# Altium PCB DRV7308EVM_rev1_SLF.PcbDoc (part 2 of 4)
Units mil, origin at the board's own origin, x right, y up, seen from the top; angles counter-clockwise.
Board outline 6187 x 6000 mil, 4 copper layers (Top Layer, Ground, Power, Bottom Layer), stack 61.2 mil thick; 306 components, 128 nets, 676 pads, 1026 vias.
Unrouted connection lines stored in the file: 208.
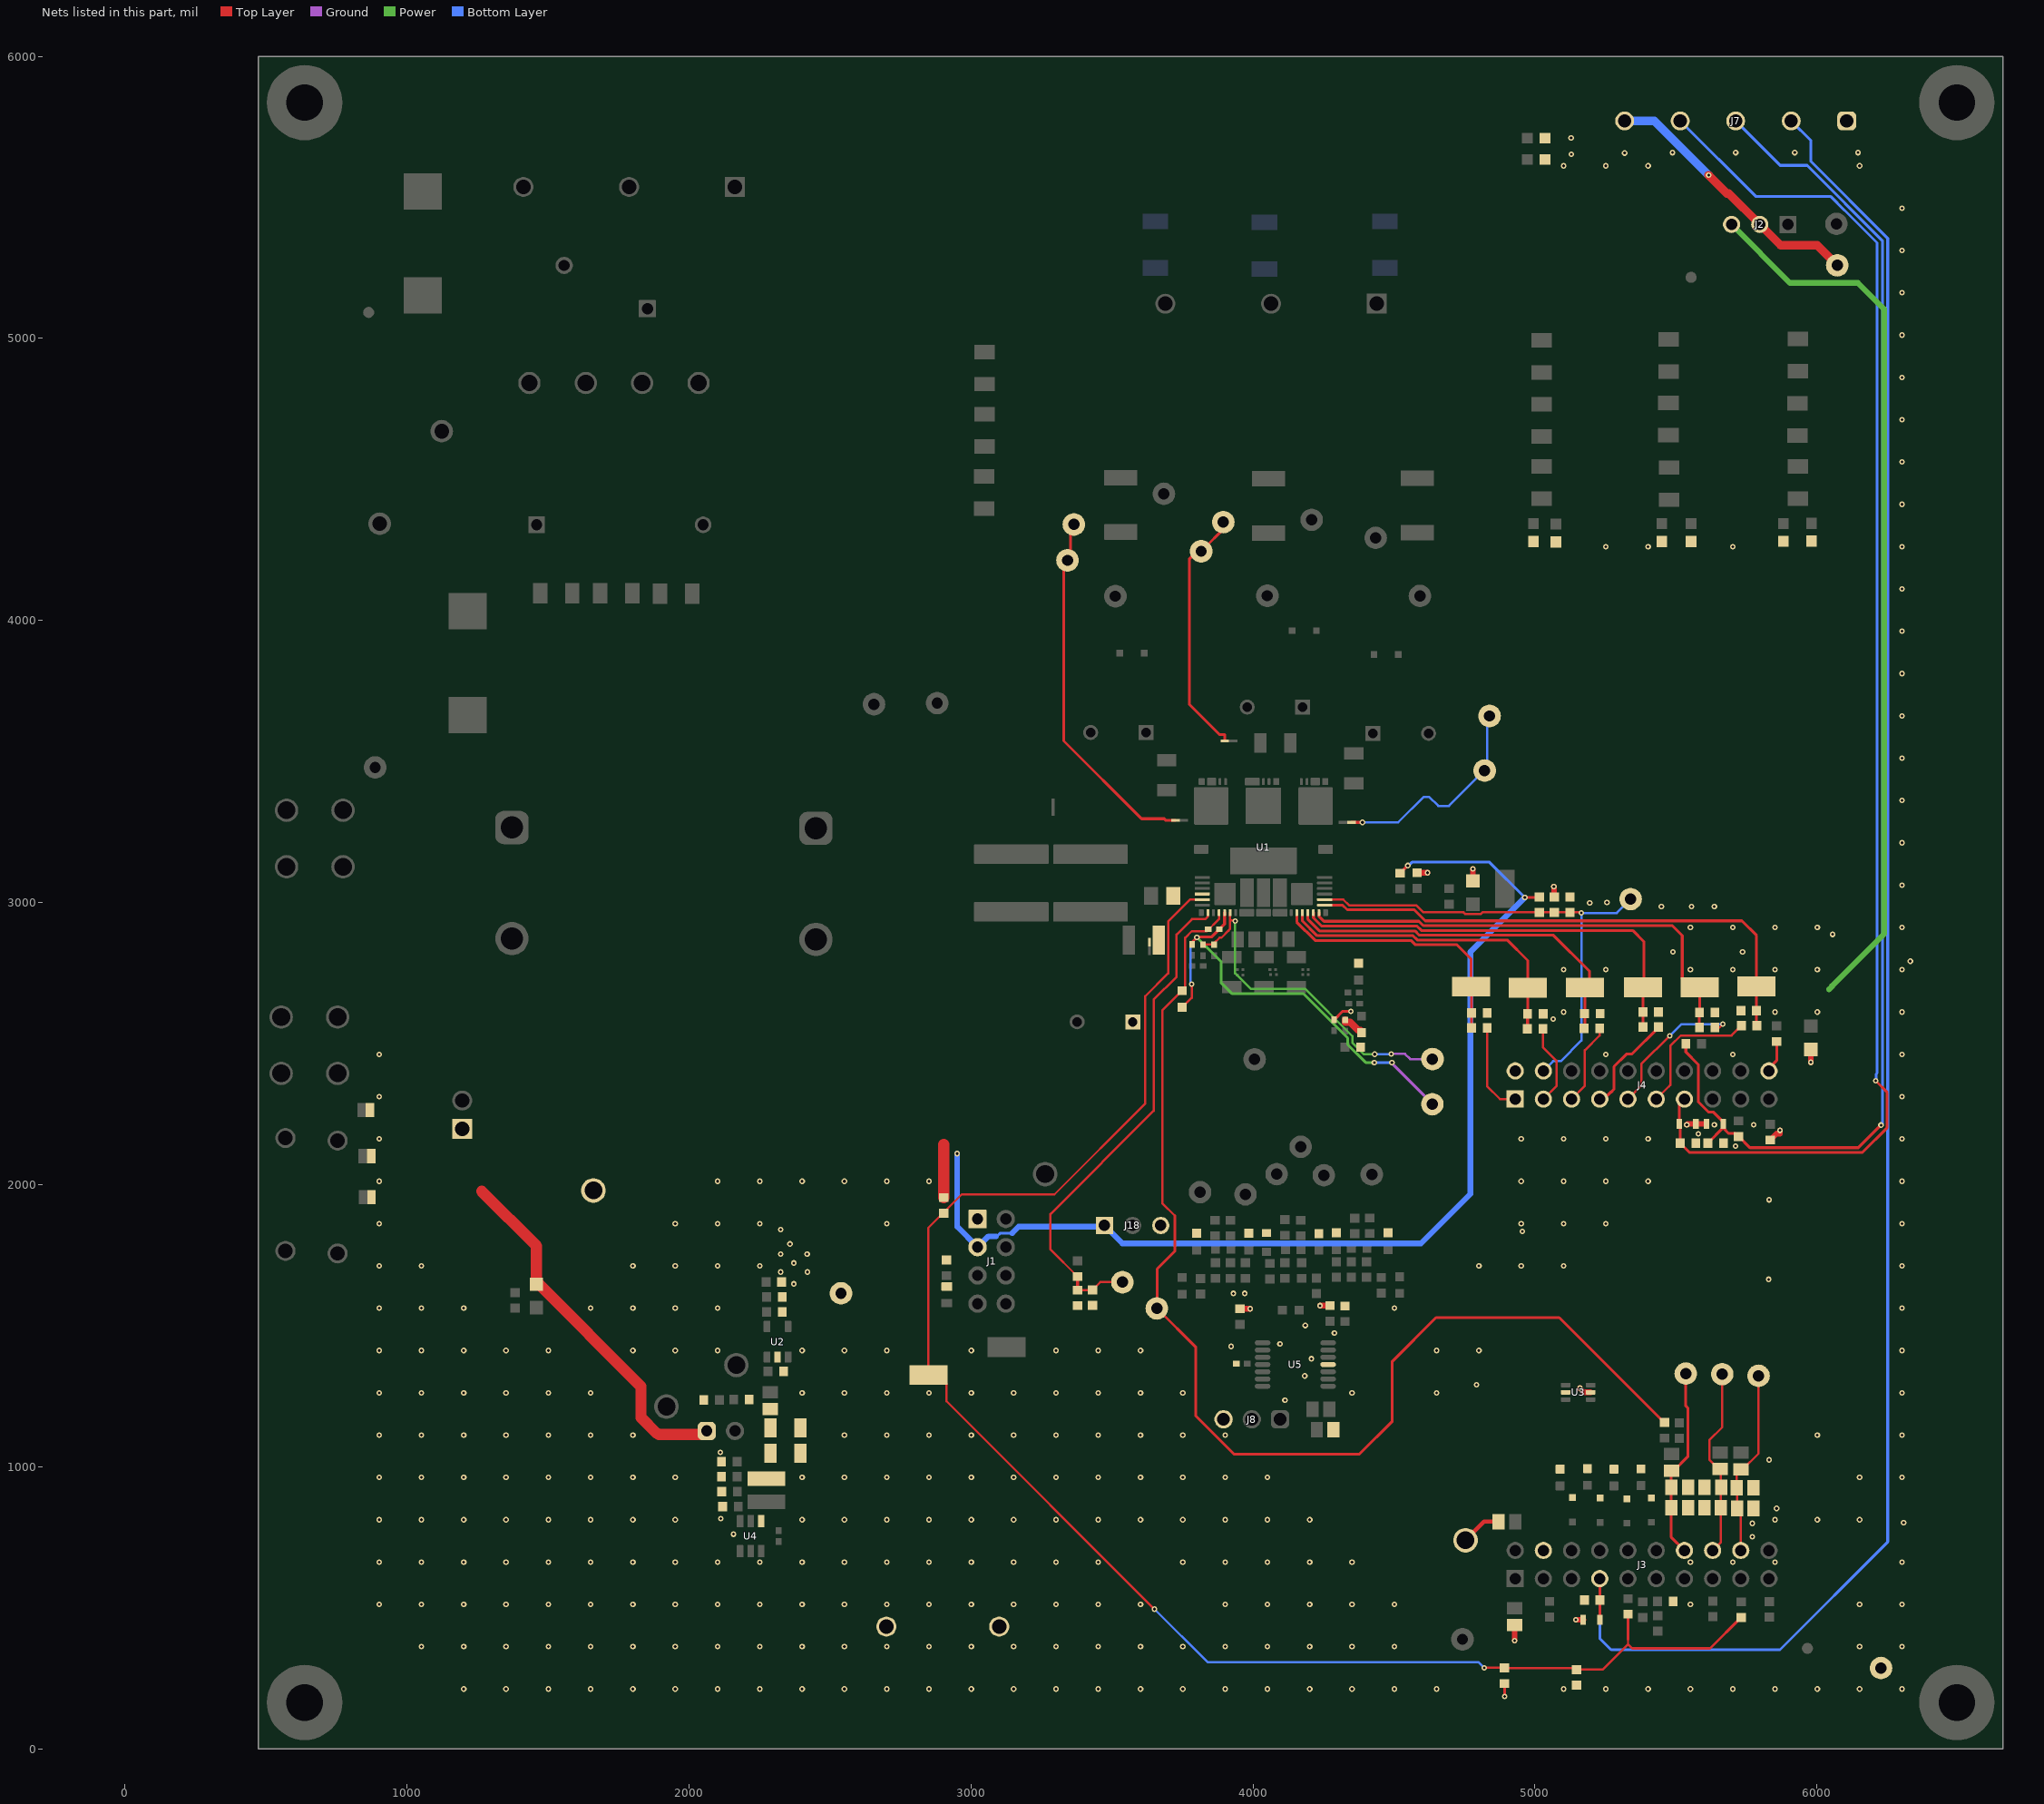
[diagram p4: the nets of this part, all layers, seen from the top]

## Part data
C1 C3 C5: library part CMP-0008509-2, "CAP, CERM, 1 uF, 25 V, +/- 10%, X7R, 1206", Cap_Case=1206, Manufacturer=AVX, Supplier Part Number 1=478-1567-1-ND, TempCo=X7R, Tolerance_%=10%, Value1="0.013 ohm", Value2=25V, ValueDisplayed=1uF
C2: library part CMP-0006343-2, "CAP, CERM, 0.1 uF, 10 V, +/- 10%, X7R, 0402", Cap_Case=0402, Manufacturer="Samsung Electro-Mechanics", TempCo=X7R, Tolerance_%=10%, Value1=Unknown, Value2=10V, ValueDisplayed=0.1uF
C4 C47 C48 C49: library part CMP-0007796-2, "CAP, CERM, 470 pF, 50 V, +/- 10%, X7R, 0805", Cap_Case=0805, Manufacturer=Kemet, Supplier Part Number 1=399-1142-1-ND, TempCo=X7R, Tolerance_%=10%, Value1="0.688 ohm", Value2=50V, ValueDisplayed=470pF
C6 C8: library part CMP-0097628-1, "2225 0.1 uF 1 kV ±10 % Tolerance X7R SMT Multilayer Ceramic Chip Capacitor", Digikey Part Number=720-1135-1-ND, Manufacturer="Vishay Vitramon", Mouser Part Number=77-VJ2225Y104KXGAT, Operating Temperature Range="-55°C to +150°C", TempCo=15%, Temperature Characteristic=X7R, Tolerance_%=10%, ValueDisplayed=0.1uF
C7 C35 C52: library part CMP-0006837-2, "CAP, CERM, 0.1 uF, 50 V, +/- 10%, X7R, 0603", Cap_Case=0603, Manufacturer="Wurth Elektronik", TempCo=X7R, Tolerance_%=10%, Value1=Unknown, Value2=50V, ValueDisplayed=0.1uF
C9: library part CMP-0007567-1, "CAP, CERM, 0.1 uF, 25 V, +/- 10%, X7R, 0805", Cap_Case=0805, Manufacturer=AVX, Supplier Part Number 1=478-3755-1-ND, TempCo=X7R, Tolerance_%=10%, Value1="0.28 ohm", Value2=25V, ValueDisplayed=0.1uF
C10: library part CMP-0009224-2, "CAP, CERM, 22 uF, 25 V, +/- 10%, X7R, 1210", Cap_Case=1210, Manufacturer=MuRata, Supplier Part Number 1=490-5313-1-ND, TempCo=X7R, Tolerance_%=10%, Value1=Unknown, Value2=25V, ValueDisplayed=22uF
C11: library part CMP-0860561-1, "CAP, CERM, 0.01 µF, 25 V,+/- 10%, X7R, 0402", Cap_Case=0402, Manufacturer="Samsung Electro-Mechanics", TempCo=X7R, Tolerance_%=10%, Value2=25V, ValueDisplayed=0.01µF
C12 C16 C17 C24 C36 C37 C40 C41 C43 C44 C46 C50: library part CMP-0104643-1, "WCAP-CSGP Multilayer Ceramic Chip Capacitor, General Purpose, size 0603, X7R, 100pF, 10VDC", Capacitance Tolerance=+/-10%, Case/Size Code=0603, Insulation Resistance=10GOhm, Manufacturer="Wurth Elektronik", Operating Temperature Max=125°C, Operating Temperature Min=-55°C, Rated Voltage (DC)=10V
C13 C14 C15 C34: library part CMP-0086483-1, "0.047µF ±10% 25V Ceramic Capacitor X7R 0603 (1608 Metric)", Manufacturer="Wurth Electronics", TempCo=15%, Tolerance_%=10%
C18 C19 C20 C21 C22 C23: library part CMP-0064933-2, "CAP, CERM, 1000 pF, 50 V,+/- 10%, X7R, 0603", Cap_Case=0603, Manufacturer="Wurth Elektronik", Supplier Part Number 1=732-8001-1-ND, TempCo=X7R, Tolerance_%=10%, Value1=Unknown, Value2=50V, ValueDisplayed=1000pF
C25 C26 C27: library part CMP-0006826-2, "CAP, CERM, 1000 pF, 16 V, +/- 10%, X7R, 0603", Cap_Case=0603, Manufacturer="Wurth Elektronik", Supplier Part Number 1=710-885012206034, TempCo=X7R, Tolerance_%=10%, Value1=Unknown, Value2=16V, ValueDisplayed=1000pF
C28 C55: library part CMP-0007505-3, "CAP, CERM, 1 uF, 10 V, +/- 10%, X7R, AEC-Q200 Grade 1, 0603", Cap_Case=0603, Manufacturer="Taiyo Yuden", Supplier Part Number 1=587-3410-1-ND, TempCo=X7R, Tolerance_%=10%, Value1=Unknown, Value2=10V, ValueDisplayed=1uF
C29 C30 C31: library part CMP-0076705-1, "CAP, CERM, 1 µF, 25 V,+/- 10%, X7R, AEC-Q200 Grade 1, 0603", Cap_Case=1.6x0.8x0.8mm, Manufacturer=TDK, Supplier Part Number 1=445-6931-1-ND, TempCo=X7R, Tolerance_%=10%, Value2=25V, ValueDisplayed=1µF
C32 C54: library part CMP-0080740-1, "CAP, CERM, 10 µF, 25 V,+/- 10%, X7R, 1206", Cap_Case=1206, Manufacturer=TDK, Supplier Part Number 1=445-7705-1-ND, TempCo=X7R, Tolerance_%=10%, Value2=25V, ValueDisplayed=10µF
C33: library part CMP-0007119-4, "CAP, CERM, 0.1 uF, 16 V, +/- 10%, X7R, 0603", Cap_Case=0603, Manufacturer="Taiyo Yuden", Supplier Part Number 1=587-1240-1-ND, TempCo=X7R, Tolerance_%=10%, Value1=Unknown, Value2=16V, ValueDisplayed=0.1uF
C38: library part CMP-0006263-2, "CAP, CERM, 2.2 uF, 10 V, +/- 10%, X5R, 0402", Cap_Case=0402, Manufacturer=TDK, Supplier Part Number 1=445-7392-1-ND, TempCo=X5R, Tolerance_%=10%, Value1=Unknown, Value2=10V, ValueDisplayed=2.2uF
C39 C42 C45: library part CMP-0006826-4, "CAP, CERM, 1000 pF, 16 V, +/- 10%, X7R, 0603", Cap_Case=0603, Manufacturer="Wurth Elektronik", Supplier Part Number 1=710-885012206034, TempCo=X7R, Tolerance_%=10%, Value1=Unknown, Value2=16V, ValueDisplayed=1000pF
C53: library part CMP-0006726-4, "CAP, CERM, 0.01 uF, 100 V, +/- 5%, X7R, 0603", Cap_Case=0603, Manufacturer=AVX, Supplier Part Number 1=478-3700-1-ND, TempCo=X7R, Tolerance_%=5%, Value1="0.098 ohm", Value2=100V, ValueDisplayed=0.01uF
C56: library part CMP-0012410-1, "CAP, Film, 0.33 uF, 630 V, +/- 20%, TH", Manufacturer=TDK, Supplier Part Number 1=495-2321-ND, Tolerance_%=20%, Value1=Unknown, Value2=630V, ValueDisplayed=0.33uF
C57 C58: library part CMP-0085509-1, "CAP, AL, 150 µF, 450 V, +/- 20%, 1.216 ohm, TH", Cap_Case=25x30mm, Manufacturer="Cornell Dubilier Electronics", Tolerance_%=20%, Value1="1.216 ohm", Value2=450V, ValueDisplayed=150µF
C59 C60 C61: library part CMP-0010527-1, "CAP, AL, 220 uF, 25 V, +/- 20%, 0.1 ohm, TH", Cap_Case=10x12.5mm, Manufacturer=Nichicon, Supplier Part Number 1=493-4497-1-ND, Tolerance_%=20%, Value1="0.1 ohm", Value2=25V, ValueDisplayed=220uF
C62 C63 C64: library part CMP-0009436-1, "CAP, CERM, 1000 pF, 2000 V, +/- 10%, X7R, 1808", Cap_Case=1808, Manufacturer=MuRata, Supplier Part Number 1=490-8145-1-ND, TempCo=X7R, Tolerance_%=10%, Value1=Unknown, Value2=2000V, ValueDisplayed=1000pF
C67: library part CMP-0010362-1, "CAP, AL, 1000 uF, 25 V, +/- 20%, TH", Cap_Case=10x20mm, Manufacturer=Chemi-Con, Supplier Part Number 1=565-1311-ND, Tolerance_%=20%, Value1=Unknown, Value2=25V, ValueDisplayed=1000uF
D2: library part CMP-0002829-1, "LED, Red, SMD", Color=red, Manufacturer=Lite-On, Supplier Part Number 1=160-1415-1-ND, Value1=W, Value2=2V
D3: library part CMP-0002888-1, "LED, Green, SMD", Color=Green, Manufacturer=Lite-On, PartNumber=LTST-C170KGKT, Supplier Part Number 1=160-1414-1-ND, Value1=W, Value2=2V
D4: library part CMP-0002890-1, "LED, Orange, SMD", Color=orange, Manufacturer=Lite-On, PartNumber=LTST-C170KFKT, Supplier Part Number 1=160-1413-1-ND, Value1=W, Value2=2V
D7: library part CMP-0029245-3, "Diode, Switching-Bridge, 600 V, 6 A, TH", Manufacturer="Diodes Inc.", Value1=6A, Value2=1V
D9 D10 D11 D12: library part CMP-0084035-2, "Diode, Schottky, 7 V, 0.01 A, SOD-323", Manufacturer="ON Semiconductor", Value1=0.01A, Value2=0.6V
D14 D15 D16: library part CMP-0005835-4, "Diode, Zener, 18 V, 200 mW, SOD-323", Manufacturer="Diodes Inc.", Power_W=200mW, Value1=0.2W
F1 F2: library part CMP-0003468-2, "Fuse, 3 A, 250VAC/VDC, SMD", Irating_A=3A, Manufacturer=Littelfuse, Supplier Part Number 1=F2910CT-ND
FID1 FID2 FID3: library part CMP-0077181-1, "Fiducial mark.  There is nothing to buy or mount.", Manufacturer=N/A
H9 H10 H11 H12: library part CMP-0003640-1, "Standoff, Hex,25mm Length, M3, Aluminum", Manufacturer=Keystone, Supplier Part Number 1=36-24438-ND
H13 H14 H15 H16: library part CMP-0003646-1, "MACHINE SCREW PAN PHILLIPS M3 5mm", Manufacturer="B&F Fastener Supply", Supplier Part Number 1=H742-ND
J1: library part CMP-0075408-2, "Header, 100mil, 4x2, Gold, TH", Color=Black, Current_A=6.3A, Manufacturer=Samtec, PartNumber=TSW-104-07-G-D, Supplier Part Number 1=SAM1028-04-ND, Voltage_V=550V
J2 J18: library part CMP-0065026-1, "Header, 2.54mm, 3x1, Tin, TH", Color=Black, Current_A=3A, Manufacturer=FCI, PartNumber=68001-403HLF, Supplier Part Number 1=609-3471-ND, Voltage_V=1.5kV
J3 J4: library part CMP-0075613-1, "Receptacle, 2.54mm, 10x2, Gold, TH", Color=Black, Current_A=6.3A, Manufacturer=Samtec, Voltage_V=550V
J5: library part CMP-0055418-2, "Banana Jack Insul Nylon Red, R/A, TH", Color=Red, Current_A=25A, Manufacturer="Cal Test Electronics", Supplier Part Number 1=BKCT3151SP-2-ND, Voltage_V=1kV
J6: library part CMP-0055528-1, "Terminal Block, 9.52mm, 3x1, R/A, TH", Color=Green, Current_A=32A, Manufacturer="Phoenix Contact", Supplier Part Number 1=277-6184-ND, Voltage_V=1kV
J7: library part CMP-0055532-1, "Terminal Block, 5mm, 5x1, R/A, TH", Color=Green, Current_A=16A, Manufacturer="Phoenix Contact", PartNumber=1792892, Supplier Part Number 1=277-2521-ND, Voltage_V=400V
J8: library part CMP-0054796-2, "Header, 2.54 mm, 3x1, Gold, TH", Color=Black, Manufacturer="Wurth Elektronik", PartNumber=61300311121, Supplier Part Number 1=732-5316-ND
J9: library part CMP-0075076-1, "Terminal Block, 2.54mm, 2x1, Brass, TH", Manufacturer="On-Shore Technology", PartNumber=OSTVN02A150, Supplier Part Number 1=ED10561-ND
J10: library part CMP-0055417-2, "Banana Jack Insul Nylon Black, R/A, TH", Color=Black, Current_A=25A, Manufacturer="Cal Test Electronics", Supplier Part Number 1=BKCT3151SP-0-ND, Voltage_V=1kV
J17: library part CMP-0075405-3, "Header, 100mil, 2x1, Gold, TH", Color=Black, Current_A=6.3A, Manufacturer=Samtec, PartNumber=TSW-102-07-G-S, Supplier Part Number 1=SAM1029-02-ND, Voltage_V=550V
J19: library part CMP-0055528-1, "Terminal Block, 9.52mm, 3x1, R/A, TH", Color=Green, Current_A=32A, Manufacturer="Phoenix Contact", PartNumber=1904150, Supplier Part Number 1=277-6184-ND, Voltage_V=1kV
L1: library part CMP-0064361-1, "Inductor, Shielded, Powdered Iron, 4.7 uH, 1.5 A, 0.162 ohm, AEC-Q200 Grade 1, SMD", Manufacturer="Wurth Elektronik", Supplier Part Number 1=732-6941-1-ND, Value1="0.162 ohm", Value2=1.5A, ValueDisplayed=4.7uH
L2 L3 L4: library part CMP-0003168-1, "Ferrite Bead, 120 ohm @ 100 MHz, 3 A, 1812", Manufacturer="Wurth Elektronik", Supplier Part Number 1=732-1641-1-ND, Value1="0.05 ohm", Value2=3A, ValueDisplayed="120 ohm"
LOGO LOGO5 LOGO7: library part CMP-0074837-1, "IEC 61010-1 Hot Surface Warning"
Logo1: library part CMP-0074844-1
Logo2: library part CMP-0074838-1, "Texas Instrument Corporate Signature"
Logo3: library part CMP-0074847-1, "FCC_disclaimer"
Logo4: library part CMP-0074769-1
LOGO6 LOGO8: library part CMP-0074835-1, "IEC 61010-1 High Voltage Warning"
MH5 MH6 MH7 MH8: library part CMP-0078423-2, "PCB Mounting Hole", Manufacturer=Any, PartNumber=N/A
NT1 NT2 NT14: library part CMP-0078142-1, "Single point connection between nets.", Manufacturer=N/A
NT3 NT4 NT5 NT6 NT7 NT8 NT9 NT10 NT11 NT12 NT13: library part CMP-0078142-4, "Single point connection between nets.", Manufacturer=N/A
R1: library part CMP-0022073-1, "RES, 162 k, 1%, 0.1 W, 0603", Manufacturer=Vishay-Dale, Power_W=100mW, Supplier Part Number 1=541-162KHCT-ND, TempCo="100 ppm/C", Tolerance_%=1%, Value2=0.1W, Value_Code=162k
R2 R48 R49 R50 R51 R54 R78 R79 R135 R137 R138 R139: library part CMP-0025874-4, "RES, 0, 5%, 0.1 W, AEC-Q200 Grade 0, 0603", Manufacturer=Panasonic, Power_W=100mW, Supplier Part Number 1=P0.0GCT-ND, TempCo="600 ppm/C", Tolerance_%=5%, Value2=0.1W, Value_Code=0000, ValueDisplayed=0
R3 R6 R37: library part CMP-0017262-1, "RES, 0.03, 1%, 0.5 W, 1206", Manufacturer="Stackpole Electronics Inc", Power_W=500mW, Supplier Part Number 1=CSR1206FK30L0CT-ND, TempCo="100 ppm/C", Tolerance_%=1%, Value2=0.5W, Value_Code=R030, ValueDisplayed=0.03
R4: library part CMP-0024951-1, "RES, 22.1 k, 0.5%, 0.1 W, 0603", Manufacturer="Yageo America", Power_W=100mW, TempCo="50 ppm/C", Tolerance_%=0.5%, Value2=0.1W, Value_Code=22k1, ValueDisplayed=22.1k
R5 R21: library part CMP-0020616-1, "RES, 0, 5%, 0.125 W, 0805", Manufacturer=Panasonic, Power_W=125mW, Supplier Part Number 1=P0.0ACT-ND, TempCo="600 ppm/C", Tolerance_%=5%, Value2=0.125W, Value_Code=0000, ValueDisplayed=0
R7 R13 R36: library part CMP-0020616-3, "RES, 0, 5%, 0.125 W, AEC-Q200 Grade 0, 0805", Manufacturer=Panasonic, Power_W=125mW, Supplier Part Number 1=P0.0ACT-ND, TempCo="600 ppm/C", Tolerance_%=5%, Value2=0.125W, Value_Code=0000, ValueDisplayed=0
R8 R45 R128: library part CMP-0026162-2, "RES, 20.0 k, 1%, 0.063 W, AEC-Q200 Grade 0, 0402", Manufacturer=Vishay-Dale, Power_W=63mW, Supplier Part Number 1=541-20.0KLCT-ND, TempCo="100 ppm/C", Tolerance_%=1%, Value2=0.063W, Value_Code=20k0, ValueDisplayed=20.0k
R9 R11: library part CMP-0025964-3, "RES, 10.2, 1%, 0.063 W, AEC-Q200 Grade 0, 0402", Manufacturer=Vishay-Dale, Power_W=63mW, Supplier Part Number 1=541-10.2LCT-ND, TempCo="100 ppm/C", Tolerance_%=1%, Value2=0.063W, Value_Code=10R2, ValueDisplayed=10.2
R10 R12 R129: library part CMP-0026676-1, "RES, 2.00 k, 1%, 0.1 W, AEC-Q200 Grade 0, 0402", Manufacturer=Panasonic, Power_W=100mW, Supplier Part Number 1=P2.00KLCT-ND, TempCo="100 ppm/C", Tolerance_%=1%, Value2=0.1W, Value_Code=2k00, ValueDisplayed=2.00k
R14 R70 R71 R72: library part CMP-0082535-1, "RES, 330, 1%, 0.125 W, 0805", Manufacturer=Vishay-Dale, Power_W=125mW, Supplier Part Number 1=541-4142-1-ND, TempCo="100 ppm/C", Tolerance_%=1%, Value2=0.125W, Value_Code=330R, ValueDisplayed=330
R15 R17: library part CMP-0078582-1, "RES, 330, 0.1%, 0.1 W, AEC-Q200 Grade 0, 0603", Manufacturer=Panasonic, Power_W=100mW, Supplier Part Number 1=P330DBCT-ND, TempCo="25 ppm/C", Tolerance_%=0.1%, Value2=0.1W, Value_Code=330R, ValueDisplayed=330
R16: library part CMP-0024300-2, "RES, 4.70 k, 0.1%, 0.1 W, 0603", Manufacturer="Yageo America", Power_W=100mW, TempCo="25 ppm/C", Tolerance_%=0.1%, Value2=0.1W, Value_Code=4k70, ValueDisplayed=4.70k
R18 R19 R20 R75 R76 R77 R120: library part CMP-0022736-4, "RES, 100, 1%, 0.1 W, 0603", Manufacturer=Yageo, Power_W=100mW, Supplier Part Number 1=311-100HRCT-ND, TempCo="100 ppm/C", Tolerance_%=1%, Value2=0.1W, Value_Code=100R, ValueDisplayed=100
R22 R121 R122: library part CMP-0018205-2, "RES, 330 k, 1%, 0.25 W, 1206", Manufacturer="Yageo America", Power_W=250mW, Supplier Part Number 1=311-330KFRCT-ND, TempCo="100 ppm/C", Tolerance_%=1%, Value2=0.25W, Value_Code=330k
R29 R30 R31: library part CMP-0025686-1, "RES, 10.0 k, 0.1%, 0.1 W, AEC-Q200 Grade 1, 0603", Manufacturer=Vishay-Dale, Power_W=100mW, Supplier Part Number 1=TNP10.0KAACT-ND, TempCo="25 ppm/C", Tolerance_%=0.1%, Value2=0.1W, Value_Code=10k0, ValueDisplayed=10.0k
R34 R41 R117 R123 R124 R125 R126 R127: library part CMP-0025830-1, "RES, 5.1 k, 5%, 0.1 W, 0603", Manufacturer=Vishay-Dale, Power_W=100mW, Supplier Part Number 1=541-5.1KGCT-ND, TempCo="200 ppm/C", Tolerance_%=5%, Value2=0.1W, Value_Code=5k10, ValueDisplayed=5.1k
R43: library part CMP-0025701-4, "RES, 10 k, 5%, 0.1 W, AEC-Q200 Grade 0, 0603", Manufacturer=Vishay-Dale, Power_W=100mW, Supplier Part Number 1=541-10KGCT-ND, TempCo="200 ppm/C", Tolerance_%=5%, Value2=0.1W, Value_Code=10k0, ValueDisplayed=10k
R44: library part CMP-0095619-1, "RES Thick Film, 68kΩ, 1%, 0.1W, 100ppm/°C, 0603", Approved Alternate Part Number=541-1.00HHCT-ND, Manufacturer=Vishay, Operating Temperature Range="-55°C to +155°C", Power=100mW, TempCo=100ppm/°C, Tolerance_%=1%, Voltage=75V
R46 R57 R58 R63 R64 R69 R118: library part CMP-0022447-4, "RES, 49.9 k, 1%, 0.1 W, AEC-Q200 Grade 0, 0603", Manufacturer=Vishay-Dale, Power_W=100mW, Supplier Part Number 1=541-49.9KHCT-ND, TempCo="100 ppm/C", Tolerance_%=1%, Value2=0.1W, Value_Code=49k9, ValueDisplayed=49.9k
R47: library part CMP-0025697-4, "RES, 0, 5%, 0.1 W, AEC-Q200 Grade 0, 0603", Manufacturer=Vishay-Dale, Power_W=100mW, Supplier Part Number 1=541-0.0GCT-ND, TempCo="200 ppm/C", Tolerance_%=5%, Value2=0.1W, Value_Code=0000, ValueDisplayed=0
R52 R55 R59 R61 R65 R67: library part CMP-0022005-4, "RES, 10.2, 1%, 0.1 W, AEC-Q200 Grade 0, 0603", Manufacturer=Vishay-Dale, Power_W=100mW, Supplier Part Number 1=541-10.2HCT-ND, TempCo="100 ppm/C", Tolerance_%=1%, Value2=0.1W, Value_Code=10R2, ValueDisplayed=10.2
R53 R56 R60 R62 R66 R68: library part CMP-0022458-4, "RES, 4.99 k, 1%, 0.1 W, AEC-Q200 Grade 0, 0603", Manufacturer=Vishay-Dale, Power_W=100mW, Supplier Part Number 1=541-4.99KHCT-ND, TempCo="100 ppm/C", Tolerance_%=1%, Value2=0.1W, Value_Code=4k99, ValueDisplayed=4.99k
R73 R74: library part CMP-0021990-4, "RES, 100 k, 1%, 0.1 W, AEC-Q200 Grade 0, 0603", Manufacturer=Vishay-Dale, Power_W=100mW, Supplier Part Number 1=541-100KHCT-ND, TempCo="100 ppm/C", Tolerance_%=1%, Value2=0.1W, Value_Code=100k
R91 R92 R93 R94 R98 R110 R111 R112 R113 R116 R130 R134: library part CMP-0018207-2, "RES, 332 k, 1%, 0.25 W, 1206", Manufacturer="Yageo America", Power_W=250mW, Supplier Part Number 1=311-332KFRCT-ND, TempCo="100 ppm/C", Tolerance_%=1%, Value2=0.25W, Value_Code=332k
R99 R100 R101 R102 R103 R104 R105 R106: library part CMP-0023308-5, "RES, 8.20 k, 1%, 0.1 W, 0603", Manufacturer=Yageo, Power_W=100mW, Supplier Part Number 1=311-8.20KHRCT-ND, TempCo="100 ppm/C", Tolerance_%=1%, Value2=0.1W, Value_Code=8k20, ValueDisplayed=8.20k
R107 R108 R109: library part CMP-0021042-1, "RES, 20.0 k, 1%, 0.125 W, 0805", Manufacturer=Vishay-Dale, Power_W=125mW, Supplier Part Number 1=541-20.0KCCT-ND, TempCo="100 ppm/C", Tolerance_%=1%, Value2=0.125W, Value_Code=20k0, ValueDisplayed=20.0k
R119: library part CMP-0022280-2, "RES, 2.67 k, 1%, 0.1 W, 0603", Manufacturer=Vishay-Dale, Power_W=100mW, Supplier Part Number 1=541-2.67KHCT-ND, TempCo="100 ppm/C", Tolerance_%=1%, Value2=0.1W, Value_Code=2k67, ValueDisplayed=2.67k
RT1: library part CMP-0002561-2, "Thermistor NTC, 5 ohm, 25%, Disc, 220x770 mil", Manufacturer="GE Sensing", Power_W=180W, Supplier Part Number 1=KC004L-ND, Tolerance_%=25%
RV1: library part CMP-0086467-2, "Var MOV 350VAC/460VDC 3500A 560V Radial Bulk", Manufacturer=TDK
SH-J1 SH-J2 SH-J3 SH-J4 SH-J5: library part CMP-0003623-3, "Shunt, 100mil, Gold plated, Black", Alternate Manufacturer=3M, Alternate PartNumber=969102-0000-DA, Manufacturer=Samtec, Supplier Part Number 1=SAM8858-ND
TP1 TP2 TP3: library part CMP-0055137-1, "Test Point, Miniature, Red, TH", Color=Red, Manufacturer=Keystone, PartNumber=5000, Supplier Part Number 1=36-5000-ND
TP4 TP5 TP6 TP7 TP9 TP10 TP29 TP32 TP34 TP35 TP40 TP41: library part CMP-0055137-2, "Test Point, Miniature, Red, TH", Color=Red, Manufacturer="Keystone Electronics", PartNumber=5000, Supplier Part Number 1=36-5000-ND
TP8 TP18 TP20 TP21 TP22 TP23 TP24 TP43 TP45: library part CMP-0055152-1, "Test Point, Miniature, SMT", Manufacturer=Keystone, PartNumber=5015, Supplier Part Number 1=36-5015TR-ND
TP11 TP12 TP13: library part CMP-0075110-1, "1mm Uninsulated Shorting Plug, 10.16mm spacing, TH", Manufacturer=Harwin, PartNumber=D3082-05, Supplier Part Number 1=952-1873-ND
TP14 TP26 TP31 TP36 TP37 TP38 TP39 TP44 TP46 TP47 TP48 TP49 TP52 TP53 TP54 TP55 TP56 TP57: library part CMP-0055139-2, "Test Point, Miniature, White, TH", Color=White, Manufacturer="Keystone Electronics", PartNumber=5002, Supplier Part Number 1=36-5002-ND
TP16 TP17: library part CMP-0055138-1, "Test Point, Miniature, Black, TH", Color=Black, Manufacturer=Keystone, PartNumber=5001, Supplier Part Number 1=36-5001-ND
TP19 TP30 TP33 TP42 TP50: library part CMP-0055146-2, "Test Point, Compact, Yellow, TH", Color=Yellow, Manufacturer="Keystone Electronics", PartNumber=5009, Supplier Part Number 1=36-5009-ND
U1: library part CMP-0098388-1, "Three-Phase, 650-V Integrated GaN FET Motor Driver, VQFN65", Manufacturer="Texas Instruments", Max Supply Voltage=18.5V, Min Supply Voltage=10.8V, Nominal Supply Current=1-5mA, Operating Temperature Range="-40°C to +125°C", Switching Frequency=20kHz
U2: library part CMP-0065093-2, "Low-Dropout Regulator, DBV0005A (SOT-23-5)", Alternate Manufacturer="Texas Instruments"
U3: library part CMP-0043118-3, "4-Channel ESD Solution for High-Speed Differential Interface, DCK0006A (SOT-SC70-6)", Breakdown Voltage(Min)(V)=9, Differential Capacitance(pF)=0.05, IO Capacitance(Typ)(pF)=0.8, IO Leakage Current(nA)=10, Manufacturer="Texas Instruments", Operating Temperature Range="-40 to 85 C", Rating=Catalog
U4: library part CMP-0094075-1, "SIMPLE SWITCHER 4.5-V to 36-V, 2-A Buck Converter in SOT-23-6 Package", Manufacturer="Texas Instruments", Max Supply Voltage=32V, Min Supply Voltage=4.5V, Nominal Supply Current=40-420uA, Operating Temperature Range="-40°C to +150°C", Output Voltage=0.6-30.4V, Switching Frequency=500kHz
U5: library part CMP-0082283-1, "4 channel, 10-MHz, Low-Noise, RRIO, CMOS Operational Amplifier for Cost-Sensitive Systems, PW0014A (TSSOP-14)", Alternate Manufacturer="Texas Instruments", Alternate PartNumber=TLV9064IPWT, Operating Temperature Range="-40 to 125 C", Rating=Catalog
ZZ1: library part CMP-0003616-3
ZZ2: library part CMP-0077236-1
ZZ3: library part CMP-0077237-1
ZZ4: library part CMP-0077238-1

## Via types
v1: diameter 20, hole 10, Top Layer to Bottom Layer, tented both sides, 563 vias
v2: diameter 20/20/20/20 (per signal layer), hole 10, Top Layer to Bottom Layer, tented both sides, 370 vias
v3: diameter 19.68, hole 7.87, Top Layer to Bottom Layer, tented both sides, 57 vias
v4: diameter 39.37, hole 19.68, Top Layer to Bottom Layer, tented both sides, 24 vias
v5: diameter 20/20/20/20 (per signal layer), hole 10, Top Layer to Bottom Layer, tented bottom, 12 vias

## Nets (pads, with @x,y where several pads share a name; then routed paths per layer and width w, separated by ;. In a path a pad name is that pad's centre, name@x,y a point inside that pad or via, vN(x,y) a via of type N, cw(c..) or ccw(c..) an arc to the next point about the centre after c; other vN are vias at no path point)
3V3: D2.1 D4.1 J2.3 J18.3 R8.2 R13.1 R29.2 R30.2 R31.2 R41.2 R47.2 R51.1 R54.2 R73.2 R117.1 R125.1 TP26.1 U3.5 | length 3762.8
  Top Layer w10: R8.2@4288,2584.69 4317.31,2614 v1(4347.27,2614) ; R117.1@4891.82,231 4891.82,186 v1(4892.82,185)
  Top Layer w20: R47.2@3953.26,1559.7 v1(3989.7,1559.7) ; v1(4237.82,1570.7) R73.2@4273.26,1570.7 ; R41.2@4582,3105.56 v1(4618.56,3105.56) ; D2.1@4780,3076.76 v1(4780,3119) ; v1(4927.82,383) R13.1@4927.82,439.07 ; v1(5066.9,3056.78) 5068,3055.69 R125.1@5068,3019.56 ; v1(5144.82,457) R31.2@5171.29,457 ; v1(5159.09,1278.38) 5173.37,1264.1 5196.66,1264.1 U3.5@5197.38,1263.38 ; v1(5538.18,2211.89) 5541.29,2215 R30.2@5608.29,2215 ; R51.1@5834.82,2158.44 5857.19,2180.81 5868.55,2180.81 v1(5868.55,2192.17) ; v1(5978.28,2433.42) D4.1@5978.28,2479.08
  Power w20: J2.3@5697,5404 5904,5197 6145.13,5197 6238,5104.13 6238,2889 6053,2704 6053,2702 6043,2692
  other v1: 2372,1648 2325,1690 2420,1690 2372,1722 2325,1754 2419,1754 2358,1789.53 2325,1840
+5V: R36.2 TP30.1 | length 144.8
  Top Layer w15: TP30.1@4753.82,739 4819.82,805 R36.2@4871.29,805
AMPIN+: R10.2 R45.1 TP37.1 U1.6 | length 1226.3
  Top Layer w8: R10.2@3824,2850.69 R45.1@3860,2850.69 ; R45.1@3863,2853.69 R45.1@3860,2850.69 ; U1.6@3918.96,2964.09 3918.96,2937 ; v1(3936.5,2934.5) 3934,2937 3918.96,2937 ; R45.1@3860,2850.69 3860,2853.7 3881.3,2875 3887.89,2875 3912.82,2899.92 3912.82,2901.12 3918.96,2907.26 3918.96,2937
  Ground w8: v1(4489.99,2463.16) 4539.17,2463.16 4557.32,2445.01 TP37.1@4636.51,2445.01
  Power w8: v1(3936.5,2934.5) 3936.5,2749.15 3991.65,2694 4184.84,2694 4352.46,2526.38 4352.46,2503.3 4393.76,2462 v1(4431.61,2462)
  Bottom Layer w8: v1(4431.61,2462) 4484.45,2462 4485.6,2463.16 v1(4489.99,2463.16)
AMPIN-: C16.1 R12.2 R128.1 TP38.1 U1.5 | length 1595.3
  Top Layer w8: C16.1@3749,2628.47 3782.84,2662.31 v1(3782.84,2710.29)
  Top Layer w10: R12.2@3784,2851.69 3784,2859 v2(3801,2876) 3802.5,2877.5 3852.43,2877.5 3872.94,2898 3873.68,2898 3899.28,2923.59 U1.5@3899.28,2964.09
  Ground w10: v1(4492.77,2432.8) 4492.77,2430.52 4636,2287.29 TP38.1@4636,2285
  Power w10: v2(3801,2876) 3801.76,2876 3886.54,2791.22 3886.54,2716.18 3925.18,2677.54 4178.02,2677.54 4336,2519.56 4336,2496.48 4399.68,2432.8 v1(4430.19,2432.8)
  Bottom Layer w8: v1@3778.66,2715.64 3778.66,2853.66 v2(3801,2876)
  Bottom Layer w10: v1(4430.19,2432.8) v1(4492.77,2432.8)
AMPOUT: C16.2 R78.2 R128.2 TP39.1 U1.4 | length 4197.4
  Top Layer w8: 3722.56,1889.44 3678.57,1933.43 3678.57,2617.1 C16.2@3749,2687.53 3759.87,2698.4 3759.87,2875 3782.87,2898 3836.48,2898 3879.59,2941.12 U1.4@3879.59,2964.09
  Top Layer w10: 3722.56,1889.44 3722.56,1763.39 3660,1700.83 3660,1560.52 3797.26,1423.27 3797.26,1179.28 3932.54,1044 4377.04,1044 4494,1160.96 4494,1373.61 4648.97,1528.57 5085.82,1528.57 5457.83,1156.56 R78.2@5458.82,1156.56
BK_OUT: C32.1 C54.1 L1.2 R1.2 R7.1
BRAKE: J4.4 R124.2 R125.2 R126.2 TP44.1 U1.25 | length 1760.5
  Top Layer w8: U1.25@4254.12,3010.35 4320.6,3010.35 4340.67,2990.28 4578.47,2990.28 4603.87,2964.88 4746.4,2964.88 4751.82,2959.46 4808.18,2959.46 4813.6,2964.88 R126.2@5124,2964.88 v1@5164.42,2964.88
  Bottom Layer w8: J4.4@5029.5,2403.32 J4.4@5029.82,2403 5064.48,2437.66 5091.25,2437.66 5164.42,2510.82 v1(5164.42,2963) 5289.98,2963 TP44.1@5339.09,3012.11
ENABLE: R2.1 R34.2 R49.1 R117.2 R123.2 TP43.1 U1.64 | length 5851.6
  Top Layer w8: TP43.1@2848.59,1325 2848.59,1846.59 2967.01,1965.01 3296.01,1965.01 3617.99,2286.99 3617.99,2667.99 3699,2749 3699,2932.94 3776.41,3010.35 U1.64@3820.02,3010.35 ; TP43.1@2850,1325 2882.5,1325 2913.5,1294 2913.5,1231.5 3648,497 3649,497 v1(3651,495) ; v1(4819.7,286.69) 4891.25,286.69 R117.2@4891.82,286.12 5141.26,286.12 R123.2@5146.82,280.56 5240.5,280.56 5329.93,369.99 5329.93,386
  Top Layer w10: 5329.93,369.99 5344.37,355.55 5620.93,355.55 R49.1@5730.82,465.44 ; 5329.93,386 R2.1@5329.93,477
  Bottom Layer w8: v1(3651,495) 3840,306 4800.39,306 v1(4819.7,286.69)
GND: C4.2 C7.2 C12.1 C13.1 C14.1 C15.1 C18.2 C19.2 C20.2 C21.2 C22.2 C23.2 C25.2 C26.2 C27.2 C28.2 C29.2 C30.2 C31.2 C32.2 C33.2 C34.1 C35.2 C36.2 C37.1 C38.1 C40.2 C41.1 C43.2 C44.1 C46.2 C47.2 C48.2 C49.2 C52.1 C53.2 C54.2 C55.2 D9.2 D10.2 D11.2 D12.2 J1.1 J3.4 J4.2 J7.1 J8.3 NT1.1 NT2.1 NT14.1 R4.1 R43.1 R44.1 R74.1 R99.1 R100.1 R101.1 R102.1 R103.1 R104.1 R105.1 R106.1 R107.1 R108.1 R109.1 R119.1 R123.1 R126.1 R129.1 TP11.1 TP11.2 TP16.1 U2.2 U3.2 U4.1 U5.11 | length 77.3
  Top Layer w10: v2(5064.29,2586.56) v2@5066.99,2586.56
  Top Layer w25: R129.1@4327,2583.69 4327,2575.63 4344.92,2575.63 4374.1,2546.44 C36.2@4381,2546.44
  Top Layer w30: J7.1@6105.44,5771 J7.1@6105.76,5770.68
  other v1: 5770.82,751 2158,760.56 5770.82,799 6307,801 2113,816 5856.82,852 5829.93,1024 2111,1051 4113.28,1235.27 4792.67,1290.26 4183.57,1321.76 4207.26,1382.5 3922.26,1426.14 4095.7,1435.42 4288.7,1473.77 4185.52,1500.52 3930.54,1614.14 3970.26,1614.14 5828.82,1664 4955.5,1834 5829.97,1946 5711,2136 5579,2180 5636.19,2211.89 5775.45,2211.89 5448,2986 5555.15,2986 5636.19,2986 5194,2999 5255,3000 5129,5653 5318.04,5657.08 5487.46,5658.76 5711.74,5658.76 5921,5658.76 6145.13,5658.76 5128,5711
  other v2: 1201.27,211.79 1351.27,211.79 1501.27,211.79 1651.27,211.79 1801.27,211.79 1951.27,211.79 2101.27,211.79 2251.27,211.79 2401.27,211.79 2551.27,211.79 2701.27,211.79 2851.27,211.79 3001.27,211.79 3151.27,211.79 3301.27,211.79 3451.27,211.79 3601.27,211.79 3751.27,211.79 3901.27,211.79 4051.27,211.79 4201.27,211.79 4351.27,211.79 4501.27,211.79 4651.27,211.79 5101.27,211.79 5251.27,211.79 5401.27,211.79 5551.27,211.79 5701.27,211.79 5851.27,211.79 6001.27,211.79 6151.27,211.79 6301.27,211.79 1051.27,361.79 1201.27,361.79 1351.27,361.79 1501.27,361.79 1651.27,361.79 1801.27,361.79 1951.27,361.79 2101.27,361.79 2251.27,361.79 2401.27,361.79 2551.27,361.79 2701.27,361.79 2851.27,361.79 3001.27,361.79 3151.27,361.79 3301.27,361.79 3451.27,361.79 3601.27,361.79 3751.27,361.79 3901.27,361.79 4051.27,361.79 4201.27,361.79 4351.27,361.79 4501.27,361.79 6151.27,361.79 6301.27,361.79 901.27,511.79 1051.27,511.79 1201.27,511.79 1351.27,511.79 1501.27,511.79 1651.27,511.79 1801.27,511.79 1951.27,511.79 2101.27,511.79 2251.27,511.79 2401.27,511.79 2551.27,511.79 2701.27,511.79 2851.27,511.79 3001.27,511.79 3151.27,511.79 3301.27,511.79 3451.27,511.79 3601.27,511.79 3901.27,511.79 4051.27,511.79 4201.27,511.79 4351.27,511.79 4501.27,511.79 5551.27,511.79 6151.27,511.79 6301.27,511.79 901.27,661.79 1051.27,661.79 1201.27,661.79 1351.27,661.79 1501.27,661.79 1651.27,661.79 1801.27,661.79 1951.27,661.79 2101.27,661.79 2251.27,661.79 2401.27,661.79 2551.27,661.79 2701.27,661.79 2851.27,661.79 3001.27,661.79 3151.27,661.79 3301.27,661.79 3451.27,661.79 3751.27,661.79 3901.27,661.79 4051.27,661.79 4201.27,661.79 4351.27,661.79 5551.27,661.79 5701.27,661.79 5851.27,661.79 6301.27,661.79 901.27,811.79 1051.27,811.79 1201.27,811.79 1351.27,811.79 1501.27,811.79 1651.27,811.79 1801.27,811.79 1951.27,811.79 2401.27,811.79 2551.27,811.79 2701.27,811.79 2851.27,811.79 3001.27,811.79 3151.27,811.79 3301.27,811.79 3451.27,811.79 3601.27,811.79 3751.27,811.79 3901.27,811.79 4051.27,811.79 4201.27,811.79 5851.27,811.79 6001.27,811.79 6151.27,811.79 901.27,961.79 1051.27,961.79 1201.27,961.79 1351.27,961.79 1501.27,961.79 1651.27,961.79 1801.27,961.79 1951.27,961.79 2401.27,961.79 2551.27,961.79 2701.27,961.79 2851.27,961.79 3001.27,961.79 3151.27,961.79 3301.27,961.79 3451.27,961.79 3601.27,961.79 3751.27,961.79 3901.27,961.79 4051.27,961.79 6151.27,961.79 6301.27,961.79 901.27,1111.79 1051.27,1111.79 1201.27,1111.79 1351.27,1111.79 1501.27,1111.79 1651.27,1111.79 1801.27,1111.79 2551.27,1111.79 2701.27,1111.79 2851.27,1111.79 3001.27,1111.79 3151.27,1111.79 3301.27,1111.79 3451.27,1111.79 3601.27,1111.79 3751.27,1111.79 3901.27,1111.79 6001.27,1111.79 6301.27,1111.79 901.27,1261.79 1051.27,1261.79 1201.27,1261.79 1351.27,1261.79 1501.27,1261.79 1651.27,1261.79 2401.27,1261.79 2551.27,1261.79 2701.27,1261.79 2851.27,1261.79 3001.27,1261.79 3151.27,1261.79 3301.27,1261.79 3451.27,1261.79 3601.27,1261.79 3751.27,1261.79 4351.27,1261.79 4651.27,1261.79 6301.27,1261.79 901.27,1411.79 1051.27,1411.79 1201.27,1411.79 1351.27,1411.79 1501.27,1411.79 1801.27,1411.79 1951.27,1411.79 2101.27,1411.79 2401.27,1411.79 2551.27,1411.79 2701.27,1411.79 3001.27,1411.79 3301.27,1411.79 3451.27,1411.79 3601.27,1411.79 4651.27,1411.79 4801.27,1411.79 6301.27,1411.79 901.27,1561.79 1051.27,1561.79 1201.27,1561.79 1651.27,1561.79 1801.27,1561.79 1951.27,1561.79 2101.27,1561.79 4501.27,1561.79 6301.27,1561.79 901.27,1711.79 1051.27,1711.79 1801.27,1711.79 1951.27,1711.79 2101.27,1711.79 2251.27,1711.79 4801.27,1711.79 4951.27,1711.79 5101.27,1711.79 6301.27,1711.79 901.27,1861.79 1951.27,1861.79 2101.27,1861.79 2251.27,1861.79 2701.27,1861.79 4951.27,1861.79 5101.27,1861.79 5251.27,1861.79 6301.27,1861.79 901.27,2011.79 2101.27,2011.79 2251.27,2011.79 2401.27,2011.79 2551.27,2011.79 2701.27,2011.79 2851.27,2011.79 4951.27,2011.79 5101.27,2011.79 5251.27,2011.79 5401.27,2011.79 6301.27,2011.79 901.27,2161.79 4951.27,2161.79 5101.27,2161.79 5251.27,2161.79 5401.27,2161.79 6301.27,2161.79 901.27,2311.79 6301.27,2311.79 901.27,2461.79 5251.27,2461.79 5701.27,2461.79 6301.27,2461.79 5101.27,2611.79 5851.27,2611.79 6001.27,2611.79 6301.27,2611.79 5101.27,2761.79 5251.27,2761.79 5551.27,2761.79 5701.27,2761.79 5851.27,2761.79 6001.27,2761.79 6301.27,2761.79 6331.1,2792 5489.02,2824.53 5736.02,2824.53 6055.09,2887.12 5551.27,2911.79 5701.27,2911.79 5851.27,2911.79 6001.27,2911.79 6301.27,2911.79 6301.27,3061.79 6301.27,3211.79 6301.27,3361.79 6301.27,3511.79 6301.27,3661.79 6301.27,3811.79 6301.27,3961.79 6301.27,4111.79 5251.27,4261.79 5401.27,4261.79 5701.27,4261.79 6301.27,4261.79 6301.27,4411.79 6301.27,4561.79 6301.27,4711.79 6301.27,4861.79 6301.27,5011.79 6301.27,5161.79 6301.27,5311.79 6301.27,5461.79 5101.27,5611.79 5251.27,5611.79 5401.27,5611.79 6151.27,5611.79
GVDD: C9.2 C10.2 C67.1 D3.1 J1.3 J9.1 J17.1 J18.1 NT13.2 R34.1 R124.1 R127.1 TP42.1 U1.63 | length 5414.4
  Top Layer w10: R127.1@4522,3103.94 v1(4549.06,3131) ; v1(4964.03,3017.96) 5013.4,3017.96 R124.1@5015,3019.56
  Top Layer w40: 1265,1976 1459,1782 D3.1@1459,1655 ; D3.1@1459,1646.68 D3.1@1459,1655 ; 1885,1119 1829.66,1174.34 1829.66,1284.34 D3.1@1459,1655 ; 1893,1114.44 2051,1114.44 J17.1@2063,1126.44 ; R34.1@2904,1953.56 2904,2142
  Bottom Layer w10: 3090.5,1814.5 3104,1828 3146.03,1828 ; v1(4549.06,3131) 4551.77,3131 4563.77,3143 4838.99,3143 v1(4964.03,3017.96)
  Bottom Layer w20: v1(2951,2110) 2951,1850.23 J1.3@3023.23,1778 3061.52,1816.29 3088.71,1816.29 ; 3146.03,1828 3169.03,1851 3477,1851 3536.61,1791.39 4595.39,1791.39 4699,1895 4771,1967 4771,2824.93 v1(4964.03,3017.96)
HALL_PWR: J2.2 J7.5 TP53.1 | length 966
  Top Layer w30: v1(5615.68,5578.78) 5680.46,5514 5687,5514 J2.2@5797,5404 5871,5330 6001,5330 TP53.1@6072,5259
  Bottom Layer w30: J7.5@5318.04,5771 5423.46,5771 v1(5615.68,5578.78)
HALLA: C25.1 J4.13 J7.4 R29.1 | length 4983.2
  Top Layer w10: J4.13@5529.82,2303 5511.29,2284.47 R29.1@5511.29,2215 5515.26,2211.03 C25.1@5515.26,2147 5515.26,2146.02 5547.58,2113.69 6160.81,2113.69 6249,2201.89 6249,2326.87 v1(6208,2367.87)
  Bottom Layer w10: J7.4@5514.89,5771 5782.39,5503.5 6047.87,5503.5 6096.37,5455 6097,5455 6213,5339 6213,2395 6209.91,2391.91 6209.91,2369.78 v1(6208,2367.87)
HALLB: C26.1 J7.3 R30.1 R138.1 R139.2 | length 4884.2
  Top Layer w10: R139.2@5535.14,2498.69 5535.14,2469.83 5579.46,2425.51 5579.46,2293.24 5616.14,2256.55 5633.67,2256.55 5667.35,2222.87 R30.1@5667.35,2215 ; C26.1@5613.26,2147 5667.35,2201.09 5687.22,2181.21 5710.89,2181.21 R138.1@5721.64,2170.47 5722.63,2170.47 5762.4,2130.69 6146.69,2130.69 v1(6227,2211)
  Bottom Layer w10: J7.3@5711.74,5767.94 J7.3@5711.74,5771 5869.22,5613.52 5965.35,5613.52 6232,5346.87 6232,2216 v1(6227,2211)
HALLC: C27.1 J3.7 J7.2 R31.1 | length 6734.2
  Top Layer w10: J3.7@5229.82,603 5229.82,527.56 C27.1@5229.93,527.45 ; R31.1@5229.93,457 C27.1@5229.93,527.45 ; C27.1@5230.38,527 C27.1@5229.93,527.45
  Bottom Layer w10: J3.7@5229.82,603 5229.82,391.06 5269.88,351 5868.63,351 6251,733.37 6251,5354.74 5978.78,5626.96 5978.78,5700.81 J7.2@5908.59,5771
ILIMIT: C35.1 R118.1 R119.2 TP36.1 U1.2 | length 1808.8
  Top Layer w8: R119.2@3378,1626 3377.56,1625.56 3430,1625.56 C35.1@3431,1626.56 3458.44,1654 TP36.1@3537,1654 ; R118.1@3378,1673.88 3282,1769.88 3282,1895.35 3648,2261.35 3648,2655.57 3729,2736.57 3729,2886.56 3783.73,2941.28 3831.28,2941.28 3840.22,2950.22 U1.2@3840.22,2964.09
  Top Layer w10: R119.2@3378,1626 R118.1@3378,1673.88
INHA: J4.1 R18.1 | length 327.4
  Top Layer w8: R18.1@4830.15,2555.59 4830.15,2348.58 4875.72,2303 J4.1@4929.82,2303
  Bottom Layer w8: J4.1@4931.12,2301.69 J4.1@4932.43,2303
INHA_DRV: C18.1 R18.2 TP8.1 U1.18 | length 951.1
  Top Layer w10: U1.18@4155.18,2964.09 4155.18,2930.78 4220.46,2865.5 4560.42,2865.5 4575.78,2850.13 4723.75,2850.13 4773.59,2800.29 TP8.1@4773.59,2701.59 4775.03,2700.15 C18.1@4775.03,2608.59 R18.2@4775.03,2555.59
INHB: J4.5 R20.1 | length 294.3
  Top Layer w8: J4.5@5129.82,2303 5177.02,2350.2 5177.02,2475.87 5229.15,2528 R20.1@5229.15,2553.59
  Bottom Layer w8: J4.5@5129.82,2303 J4.5@5132.43,2303
INHB_DRV: C20.1 R20.2 TP18.1 U1.20 | length 1308.9
  Top Layer w10: U1.20@4194.55,2964.09 4194.55,2940.45 4235.5,2899.5 4574.5,2899.5 4589.87,2884.13 5065.64,2884.13 5192.59,2757.19 5192.59,2713.59 TP18.1@5177.59,2698.59 5177.59,2557.15 R20.2@5174.03,2553.59
INHC: J4.9 R76.1 | length 528.1
  Top Layer w8: J4.9@5329.82,2303 5377.02,2350.2 5377.02,2427.37 v1@5477.3,2527.66 ; R76.1@5638.15,2555.6 R76.1@5638.15,2556.59 5654.21,2556.59 v1(5666.49,2568.87)
  Bottom Layer w8: J4.9@5331.12,2301.69 J4.9@5332.43,2303 ; v1(5477.68,2527.28) 5519.27,2568.87 v1(5666.49,2568.87)
INHC_DRV: C22.1 R76.2 TP22.1 U1.22 | length 1701.2
  Top Layer w10: U1.22@4233.92,2964.09 4233.92,2951.21 4251.63,2933.5 4588.58,2933.5 4603.95,2918.13 5486.76,2918.13 5522.09,2882.81 5522.09,2729.59 5552.09,2699.59 TP22.1@5584.59,2699.59 5584.59,2611.15 C22.1@5583.03,2609.59 R76.2@5583.03,2556.59
INLA: J4.3 R19.1 | length 294.8
  Top Layer w8: R19.1@5028.15,2552.59 5028.15,2486.96 5075.91,2439.2 5075.91,2349.1 J4.3@5029.82,2303
  Bottom Layer w8: J4.3@5029.82,2303 5029.82,2300.39 J4.3@5032.43,2303
INLA_DRV: C19.1 R19.2 TP21.1 U1.19 | length 1129.3
  Top Layer w10: U1.19@4174.87,2964.09 4174.87,2935.13 4227.5,2882.5 4567.46,2882.5 4582.82,2867.13 4901.56,2867.13 4974.59,2794.11 TP21.1@4974.59,2697.59 4974.59,2606.08 C19.1@4973.8,2605.29 4973.8,2553.36 R19.2@4973.03,2552.59
INLB: J4.7 R75.1 | length 367.1
  Top Layer w10: J4.7@5229.82,2303 5243.63,2303 5267.53,2326.91 5269.32,2326.91 5280.33,2337.91 5280.33,2418.24 5324.46,2462.38 5342.92,2462.38 5438.15,2557.6 R75.1@5438.15,2558.59 R75.1@5440.59,2556.15
  Bottom Layer w10: J4.7@5231.12,2301.69 J4.7@5232.43,2303
INLB_DRV: C21.1 R75.2 TP20.1 U1.21 | length 1529.4
  Top Layer w10: U1.21@4214.24,2964.09 4214.24,2945.34 4243.07,2916.5 4581.54,2916.5 4596.91,2901.13 5346.31,2901.13 5386,2861.44 5386,2702 TP20.1@5383.59,2699.59 5383.59,2612.15 C21.1@5383.03,2611.59 R75.2@5383.03,2558.59
INLC: J4.11 R77.1 | length 492
  Top Layer w8: J4.11@5429.82,2303 5474.82,2348 5475,2348 5480,2353 5480,2491.58 5517.27,2528.86 5696.86,2528.86 5719.27,2551.27 5720.25,2551.27 5732,2563.02 R77.1@5732,2564
INLC_DRV: C23.1 R77.2 TP23.1 U1.24 | length 1895.5
  Top Layer w10: U1.24@4254.12,2990.67 4317.66,2990.67 4334.04,2974.28 4571.84,2974.28 4610.99,2935.13 5733.89,2935.13 5785.59,2883.43 TP23.1@5785.59,2702.59 C23.1@5785.59,2618.03 ; C23.1@5785.17,2616.59 5785.17,2565.95 R77.2@5787.12,2564 R77.2@5787.68,2563.44
ISENA: C47.1 J3.14 R70.1 R107.2 TP55.1 | length 678.5
  Top Layer w10: J3.14@5529.82,703 5483.29,749.53 C47.1@5483.29,927 5483.29,984.94 R70.1@5483.82,985.47 5492.29,985.47 5541.82,1035 5541.82,1208.11 5534.82,1215.11 TP55.1@5534.82,1330 ; J3.14@5529.87,703.06 J3.14@5529.93,703
ISENB: C48.1 J3.16 R71.1 R108.2 TP56.1 | length 676.5
  Top Layer w8: J3.16@5629.82,703 5659.35,732.53 5659.35,988.94 R71.1@5656.82,991.47 5651.1,991.47 5618.26,1024.32 5618.26,1094.14 5663.82,1139.7 TP56.1@5663.82,1328
ISENC: C49.1 J3.18 R72.1 R109.2 TP57.1 | length 660.5
  Top Layer w8: J3.18@5729.82,703 5729.82,838.47 R109.2@5716.29,852 5716.29,924 C49.1@5715.29,925 5715.29,974.94 R72.1@5730.82,990.47 5736.53,990.47 5792.82,1046.76 TP57.1@5792.82,1322
K_OUTA: NT9.2 TP4.1 TP5.1 | length 1294.6
  Top Layer w10: TP5.1@3364.77,4340.4 3353.42,4329.05 3353.42,4224.53 TP4.1@3342.08,4213.18 3329,4200.1 3329,3573 3605,3297 3685,3297 3690,3292 NT9.2@3725,3292
K_OUTB: NT10.2 TP6.1 TP7.1 | length 924
  Top Layer w10: TP7.1@3811.2,4254.2 3774,4217 3774,3703.34 3882.34,3595 3900,3595 NT10.2@3900,3573 ; TP7.1@3816.29,4245.27 3905.54,4334.52 TP6.1@3905.54,4348.54 ; TP6.1@3892.63,4346.56 TP6.1@3910.07,4364
K_OUTC: NT11.2 TP9.1 TP10.1 | length 776.3
  Top Layer w10: NT11.2@4349,3284 v1(4388,3284)
  Bottom Layer w8: v1(4388,3284) 4514.9,3284 4605.9,3375 4624.41,3375 4656.93,3342.48 4695,3342.48 4820.52,3468 TP10.1@4821.5,3468 4830.24,3476.74 4830.24,3652.68 TP9.1@4838.99,3661.43
MCU_LED: J4.20 R17.1 | length 129.6
  Top Layer w10: J4.20@5820.06,2412.76 J4.20@5829.82,2403 5829.82,2412.62 5857.19,2439.99 R17.1@5857.19,2507.47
